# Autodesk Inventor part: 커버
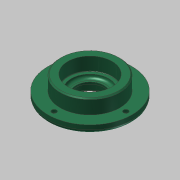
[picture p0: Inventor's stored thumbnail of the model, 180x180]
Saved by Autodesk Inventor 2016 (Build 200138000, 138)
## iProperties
Company: 한국ATC센터
Created: 2016-04
Part Number: 커버
Document SubType Name: Modeling
Designer: mdu
Density: 7.86 g/cm^3
Mass: 351.567 g
Surface Area: 161.165 cm^2
Volume: 44.7286 cm^3
Material: 강철, 연강
Appearance: 강철
Author: mdu
Revision Number: 1
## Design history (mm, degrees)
sketch "스케치1"
  geometry: C1 r 38 at (0, 0); 1 further point
  constraints: 1 centre point, 1 coincident
  dimensions: "d0" = 76 diameter of C1
extrude "돌출1" new body sketch "스케치1" distance "d1" = 7; taper "d2" = 0 deg
sketch "스케치2"
  geometry: C1 r 27 at (0, 0); 1 further point
  constraints: 1 centre point, 1 coincident
  dimensions: "d3" = 54 diameter of C1
extrude "돌출2" join sketch "스케치2" distance "d4" = 13; taper "d5" = 0 deg
sketch "스케치3"
  geometry: C1 r 20 at (0, 0); 1 further point
  constraints: 1 centre point, 1 coincident
  dimensions: "d6" = 40 diameter of C1
extrude "돌출3" join sketch "스케치3" distance "d7" = 5; taper "d8" = 0 deg
hole "구멍1" diameter "d11" = 25; stored, may be unused: countersink angle "d15" = 90 deg, drill point angle "d17" = 118 deg; dims "d9" = 10, "d10" = 10, "d12" = 6, "d13" = 32, "d14" = 8.3, "d16" = 8
hole "구멍2" diameter "d20" = 34; stored, may be unused: countersink angle "d24" = 90 deg, drill point angle "d26" = 0 deg; dims "d18" = 10, "d19" = 10, "d21" = 6, "d22" = 40, "d23" = 12, "d25" = 3
fillet "모깎기2" dims "d34" = 3
fillet "모깎기1" dims "d27" = 0.3
chamfer "모따기1" distance "d28" = 1; stored, may be unused: second distance "d29" = 2, angle "d30" = 45 deg
chamfer "모따기2" distance "d31" = 1.2; stored, may be unused: second distance "d32" = 2, angle "d33" = 30 deg
sketch "스케치4" dims "d35" = 65
  geometry: 3 further points
  constraints: 2 horizontal alignment, 1 coincident, 2 other
hole "구멍3" sketch "스케치4" at (32.5, 0) diameter "d36" = 4.5; stored, may be unused: countersink angle "d40" = 90 deg, drill point angle "d42" = 118 deg; dims "d37" = 6, "d38" = 8, "d39" = 4.4, "d41" = 13
node "솔리드1"
pattern_circular "원형 패턴1" dims angle "d44" = 360 deg
